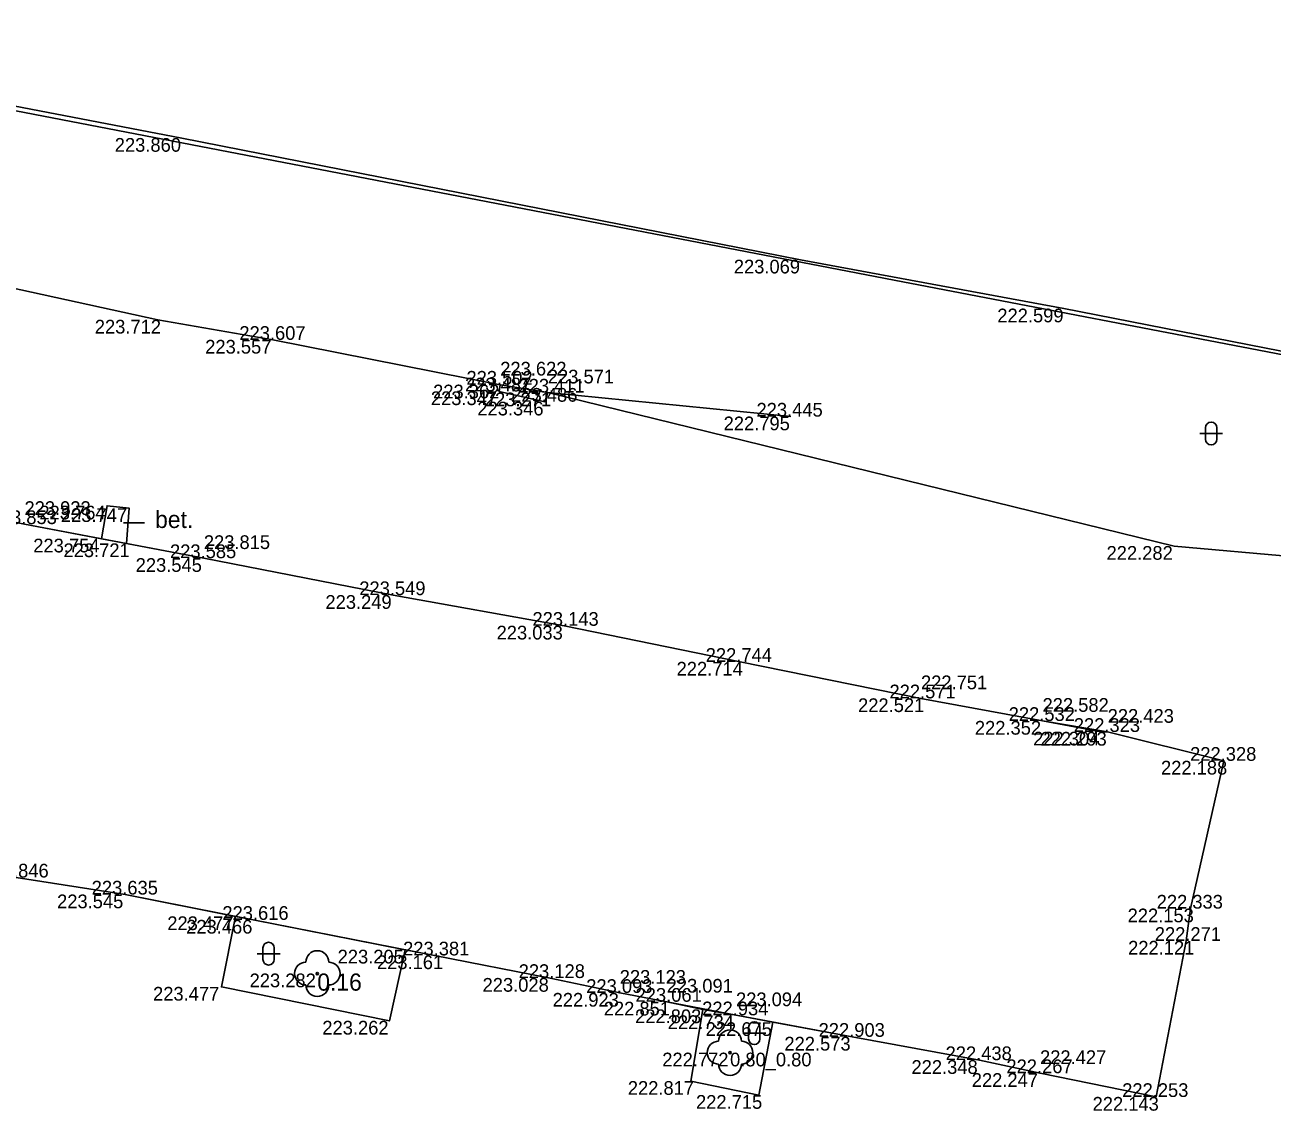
# Model space of a CAD drawing. Extents: x -599516 to -599132, y -1163668 to -1163119.
# Drawn here: x -599329.8 to -599302.48, y -1163179.4 to -1163155.61 of the extents above; entities that cross this region are included whole.
import ezdxf

# ---------------------------------------------------------------- set-up
doc = ezdxf.new("R2010")
doc.units = 0
for name, color, linetype in [('_ZEMERENI OBLAST', 7, 'Continuous'), ('Bod-oznac1', 7, 'Continuous'), ('Bod-oznac2', 7, 'Continuous'), ('Bod-oznac3', 7, 'Continuous'), ('Bod-vyska1', 7, 'Continuous'), ('Bod-vyska2', 7, 'Continuous'), ('Bod-vyska3', 7, 'Continuous'), ('Z_cela-hrobu-dolni-linie', 7, 'Continuous'), ('Z_cela-hrobu-horni-linie', 7, 'Continuous'), ('Z_komunikace', 7, 'Continuous'), ('Z_kultury-znacky', 7, 'Continuous'), ('Z_nove-stromy-prumer-kmene', 7, 'Continuous'), ('Z_obvod-kmene-spodek-ve-vysce1_2m', 7, 'Continuous'), ('Z_popis-budov-povrchu', 7, 'Continuous'), ('Z_povrchy-rozhrani-typu', 7, 'Continuous'), ('Z_stromy-kere', 7, 'Continuous'), ('Z_stromy-nove-vysazene', 7, 'Continuous'), ('Z_vol-lin-odkazova-cara', 7, 'Continuous'), ('Z_zdi-ohradni', 7, 'Continuous'), ('Z_zpevnene-plochy', 7, 'Continuous')]:
    doc.layers.add(name, color=color, linetype=linetype)

msp = doc.modelspace()

# ---------------------------------------------------------------- linework, layer by layer
at = {"layer": '_ZEMERENI OBLAST'}
msp.add_lwpolyline([(-599246.21, -1163173.61), (-599310.76, -1163161.2), (-599382.471, -1163147.382), (-599418.511, -1163140.298), (-599415.805, -1163126.425), (-599441.73, -1163121.594), (-599445.004, -1163135.25), (-599483.712, -1163127.751), (-599506.25, -1163123.345), (-599510.771, -1163146.476), (-599502.636, -1163301.975), (-599510.038, -1163302.355), (-599510.12, -1163309.17), (-599515.16, -1163309.664), (-599511.204, -1163380.278), (-599506.35, -1163380.56), (-599506.01, -1163391.1), (-599497.946, -1163390.674), (-599491.96, -1163502.01)], dxfattribs=at)
at = {"layer": 'Bod-oznac1'}
for p, q in [((-599326.361, -1163158.089), (-599326.361, -1163158.089)), ((-599312.815, -1163160.754), (-599312.815, -1163160.754)), ((-599307.042, -1163161.825), (-599307.042, -1163161.825)), ((-599326.887, -1163162.07), (-599326.887, -1163162.07)), ((-599324.365, -1163162.509), (-599324.365, -1163162.509)), ((-599319.412, -1163163.637), (-599319.412, -1163163.637)), ((-599319.387, -1163163.49), (-599319.387, -1163163.49)), ((-599318.345, -1163163.663), (-599318.345, -1163163.663)), ((-599318.407, -1163163.863), (-599318.407, -1163163.863)), ((-599313.023, -1163164.189), (-599313.023, -1163164.189)), ((-599327.997, -1163166.141), (-599327.997, -1163166.141)), ((-599327.512, -1163166.196), (-599327.512, -1163166.196)), ((-599328.119, -1163166.863), (-599328.119, -1163166.863)), ((-599327.573, -1163166.966), (-599327.573, -1163166.966)), ((-599304.627, -1163167.024), (-599304.627, -1163167.024)), ((-599325.878, -1163167.289), (-599325.878, -1163167.289)), ((-599321.733, -1163168.099), (-599321.733, -1163168.099)), ((-599317.987, -1163168.77), (-599317.987, -1163168.77)), ((-599314.134, -1163169.56), (-599314.134, -1163169.56)), ((-599310.173, -1163170.359), (-599310.173, -1163170.359)), ((-599307.511, -1163170.854), (-599307.511, -1163170.854)), ((-599306.225, -1163171.091), (-599306.225, -1163171.091)), ((-599306.085, -1163171.094), (-599306.085, -1163171.094)), ((-599303.538, -1163171.727), (-599303.538, -1163171.727)), ((-599327.599, -1163174.655), (-599327.599, -1163174.655)), ((-599325.182, -1163175.133), (-599325.182, -1163175.133)), ((-599304.27, -1163174.963), (-599304.27, -1163174.963)), ((-599324.795, -1163175.21), (-599324.795, -1163175.21)), ((-599304.363, -1163175.67), (-599304.363, -1163175.67)), ((-599321.468, -1163175.865), (-599321.468, -1163175.865)), ((-599320.825, -1163175.988), (-599320.825, -1163175.988)), ((-599323.394, -1163176.385), (-599323.394, -1163176.385)), ((-599318.294, -1163176.483), (-599318.294, -1163176.483)), ((-599325.493, -1163176.678), (-599325.493, -1163176.678)), ((-599316.77, -1163176.81), (-599316.77, -1163176.81)), ((-599315.742, -1163177.003), (-599315.742, -1163177.003)), ((-599314.954, -1163177.171), (-599314.954, -1163177.171)), ((-599314.224, -1163177.3), (-599314.224, -1163177.3)), ((-599321.813, -1163177.421), (-599321.813, -1163177.421)), ((-599313.417, -1163177.452), (-599313.417, -1163177.452)), ((-599311.681, -1163177.771), (-599311.681, -1163177.771)), ((-599314.354, -1163178.118), (-599314.354, -1163178.118)), ((-599308.888, -1163178.282), (-599308.888, -1163178.282)), ((-599307.566, -1163178.567), (-599307.566, -1163178.567)), ((-599315.214, -1163178.741), (-599315.214, -1163178.741)), ((-599313.721, -1163179.047), (-599313.721, -1163179.047)), ((-599305.026, -1163179.088), (-599305.026, -1163179.088))]:
    msp.add_line(p, q, dxfattribs=at)
at = {"layer": 'Bod-oznac2'}
for p, q in [((-599324.365, -1163162.509), (-599324.365, -1163162.509)), ((-599319.412, -1163163.637), (-599319.412, -1163163.637)), ((-599319.387, -1163163.49), (-599319.387, -1163163.49)), ((-599318.345, -1163163.663), (-599318.345, -1163163.663)), ((-599318.407, -1163163.863), (-599318.407, -1163163.863)), ((-599313.023, -1163164.189), (-599313.023, -1163164.189)), ((-599325.878, -1163167.289), (-599325.878, -1163167.289)), ((-599321.733, -1163168.099), (-599321.733, -1163168.099)), ((-599317.987, -1163168.77), (-599317.987, -1163168.77)), ((-599314.134, -1163169.56), (-599314.134, -1163169.56)), ((-599310.173, -1163170.359), (-599310.173, -1163170.359)), ((-599307.511, -1163170.854), (-599307.511, -1163170.854)), ((-599306.085, -1163171.094), (-599306.085, -1163171.094)), ((-599303.538, -1163171.727), (-599303.538, -1163171.727)), ((-599327.599, -1163174.655), (-599327.599, -1163174.655)), ((-599304.27, -1163174.963), (-599304.27, -1163174.963)), ((-599324.795, -1163175.21), (-599324.795, -1163175.21)), ((-599304.363, -1163175.67), (-599304.363, -1163175.67)), ((-599320.825, -1163175.988), (-599320.825, -1163175.988)), ((-599318.294, -1163176.483), (-599318.294, -1163176.483)), ((-599316.77, -1163176.81), (-599316.77, -1163176.81)), ((-599315.742, -1163177.003), (-599315.742, -1163177.003)), ((-599314.224, -1163177.3), (-599314.224, -1163177.3)), ((-599311.681, -1163177.771), (-599311.681, -1163177.771)), ((-599308.888, -1163178.282), (-599308.888, -1163178.282)), ((-599307.566, -1163178.567), (-599307.566, -1163178.567)), ((-599305.026, -1163179.088), (-599305.026, -1163179.088))]:
    msp.add_line(p, q, dxfattribs=at)
at = {"layer": 'Bod-oznac3'}
for p, q in [((-599319.387, -1163163.49), (-599319.387, -1163163.49)), ((-599318.345, -1163163.663), (-599318.345, -1163163.663)), ((-599325.878, -1163167.289), (-599325.878, -1163167.289)), ((-599310.173, -1163170.359), (-599310.173, -1163170.359)), ((-599307.511, -1163170.854), (-599307.511, -1163170.854)), ((-599306.085, -1163171.094), (-599306.085, -1163171.094)), ((-599316.77, -1163176.81), (-599316.77, -1163176.81)), ((-599315.742, -1163177.003), (-599315.742, -1163177.003)), ((-599314.224, -1163177.3), (-599314.224, -1163177.3)), ((-599307.566, -1163178.567), (-599307.566, -1163178.567))]:
    msp.add_line(p, q, dxfattribs=at)
at = {"layer": 'Z_cela-hrobu-dolni-linie'}
msp.add_line((-599327.573, -1163166.966), (-599328.119, -1163166.863), dxfattribs=at)
for points in [[(-599313.023, -1163164.189), (-599318.345, -1163163.663), (-599319.387, -1163163.49)], [(-599325.182, -1163175.133), (-599324.795, -1163175.21), (-599321.468, -1163175.865)], [(-599314.954, -1163177.171), (-599314.224, -1163177.3), (-599313.417, -1163177.452)]]:
    msp.add_lwpolyline(points, dxfattribs=at)
at = {"layer": 'Z_cela-hrobu-horni-linie'}
for p, q in [((-599317.987, -1163168.77), (-599321.733, -1163168.099)), ((-599314.134, -1163169.56), (-599317.987, -1163168.77))]:
    msp.add_line(p, q, dxfattribs=at)
for points in [[(-599313.023, -1163164.189), (-599318.345, -1163163.663), (-599319.387, -1163163.49), (-599324.365, -1163162.509)], [(-599321.733, -1163168.099), (-599325.878, -1163167.289), (-599325.878, -1163167.289), (-599329.806, -1163166.543), (-599329.806, -1163166.543), (-599332.367, -1163166.038)], [(-599314.134, -1163169.56), (-599310.173, -1163170.359), (-599310.173, -1163170.359), (-599307.511, -1163170.854), (-599307.511, -1163170.854), (-599306.085, -1163171.094), (-599306.085, -1163171.094), (-599303.538, -1163171.727), (-599304.27, -1163174.963)], [(-599324.795, -1163175.21), (-599327.599, -1163174.655)], [(-599320.825, -1163175.988), (-599324.795, -1163175.21)], [(-599304.363, -1163175.67), (-599305.026, -1163179.088), (-599307.566, -1163178.567), (-599307.566, -1163178.567), (-599308.888, -1163178.282)], [(-599311.681, -1163177.771), (-599314.224, -1163177.3), (-599314.224, -1163177.3), (-599315.742, -1163177.003), (-599315.742, -1163177.003), (-599316.77, -1163176.81), (-599316.77, -1163176.81), (-599318.294, -1163176.483), (-599320.825, -1163175.988)]]:
    msp.add_lwpolyline(points, dxfattribs=at)
at = {"layer": 'Z_komunikace'}
for points in [[(-599318.345, -1163163.663), (-599318.407, -1163163.863), (-599319.412, -1163163.637), (-599319.387, -1163163.49), (-599324.365, -1163162.509), (-599326.887, -1163162.07), (-599331.661, -1163161.023), (-599334.295, -1163160.601), (-599343.555, -1163158.724), (-599347.526, -1163157.941), (-599355.139, -1163156.542), (-599355.776, -1163156.429)], [(-599350.949, -1163162.537), (-599348.273, -1163162.99), (-599344.246, -1163163.763), (-599341.621, -1163164.249), (-599340.597, -1163164.419), (-599340.446, -1163163.738), (-599339.942, -1163163.851), (-599340.058, -1163164.536), (-599339.005, -1163164.764), (-599337.656, -1163165.017), (-599335.018, -1163165.53), (-599333.752, -1163165.793), (-599332.367, -1163166.038), (-599329.806, -1163166.543), (-599328.119, -1163166.863)], [(-599287.479, -1163169.726), (-599290.103, -1163169.086), (-599296.726, -1163167.729), (-599304.627, -1163167.024), (-599318.345, -1163163.663)], [(-599327.573, -1163166.966), (-599325.878, -1163167.289), (-599321.733, -1163168.099), (-599317.987, -1163168.77), (-599314.134, -1163169.56), (-599310.173, -1163170.359), (-599307.511, -1163170.854), (-599306.225, -1163171.091), (-599306.085, -1163171.094), (-599303.538, -1163171.727)], [(-599325.182, -1163175.133), (-599327.599, -1163174.655), (-599329.985, -1163174.282), (-599331.641, -1163174.239), (-599331.867, -1163175.607), (-599333.3, -1163175.262), (-599333.081, -1163173.758), (-599335.268, -1163173.304), (-599337.854, -1163172.76), (-599339.178, -1163172.519), (-599340.818, -1163172.194), (-599341.143, -1163173.716), (-599342.602, -1163173.415), (-599342.442, -1163171.866), (-599344.484, -1163171.488), (-599345.521, -1163171.291)], [(-599305.026, -1163179.088), (-599304.363, -1163175.67), (-599304.27, -1163174.963), (-599303.538, -1163171.727)], [(-599305.026, -1163179.088), (-599307.566, -1163178.567), (-599308.888, -1163178.282), (-599311.681, -1163177.771), (-599313.417, -1163177.452), (-599313.721, -1163179.047), (-599315.214, -1163178.741), (-599314.954, -1163177.171), (-599315.742, -1163177.003), (-599316.77, -1163176.81), (-599318.294, -1163176.483), (-599320.825, -1163175.988), (-599321.468, -1163175.865), (-599321.813, -1163177.421), (-599325.493, -1163176.678), (-599325.182, -1163175.133)]]:
    msp.add_lwpolyline(points, dxfattribs=at)
at = {"layer": 'Z_kultury-znacky'}
for p, q in [((-599303.942, -1163164.433), (-599303.942, -1163164.683)), ((-599303.692, -1163164.433), (-599303.692, -1163164.683)), ((-599304.067, -1163164.558), (-599303.567, -1163164.558)), ((-599324.71, -1163175.95), (-599324.21, -1163175.95)), ((-599324.585, -1163175.825), (-599324.585, -1163176.075)), ((-599324.335, -1163175.825), (-599324.335, -1163176.075)), ((-599313.949, -1163177.566), (-599313.949, -1163177.816)), ((-599313.699, -1163177.566), (-599313.699, -1163177.816)), ((-599314.074, -1163177.691), (-599313.574, -1163177.691))]:
    msp.add_line(p, q, dxfattribs=at)
for centre, start, end in [((-599303.817, -1163164.433), 0, 180), ((-599303.817, -1163164.683), 180, 0), ((-599324.46, -1163175.825), 0, 180), ((-599324.46, -1163176.075), 180, 0), ((-599313.824, -1163177.566), 0, 180), ((-599313.824, -1163177.816), 180, 0)]:
    msp.add_arc(centre, 0.125, start, end, dxfattribs=at)
at = {"layer": 'Z_povrchy-rozhrani-typu'}
msp.add_lwpolyline([(-599328.119, -1163166.863), (-599327.997, -1163166.141), (-599327.512, -1163166.196), (-599327.573, -1163166.966)], dxfattribs=at)
at = {"layer": 'Z_stromy-kere'}
msp.add_circle((-599314.354, -1163178.118), 0.025, dxfattribs=at)
for centre, start, end in [((-599314.354, -1163177.868), 0, 180), ((-599314.604, -1163178.118), 90, 270), ((-599314.104, -1163178.118), 270, 90), ((-599314.354, -1163178.368), 180, 0)]:
    msp.add_arc(centre, 0.25, start, end, dxfattribs=at)
at = {"layer": 'Z_stromy-nove-vysazene'}
msp.add_circle((-599323.394, -1163176.385), 0.025, dxfattribs=at)
for centre, start, end in [((-599323.394, -1163176.135), 0, 180), ((-599323.644, -1163176.385), 90, 270), ((-599323.144, -1163176.385), 270, 90), ((-599323.394, -1163176.635), 180, 0)]:
    msp.add_arc(centre, 0.25, start, end, dxfattribs=at)
at = {"layer": 'Z_vol-lin-odkazova-cara'}
msp.add_line((-599327.639, -1163166.512), (-599327.18, -1163166.512), dxfattribs=at)
at = {"layer": 'Z_zdi-ohradni'}
for points in [[(-599414.8, -1163140.976), (-599394.798, -1163144.985), (-599376.174, -1163148.484), (-599363.541, -1163150.911), (-599348.224, -1163153.888), (-599326.361, -1163158.089), (-599312.815, -1163160.754)], [(-599298.256, -1163163.544), (-599307.042, -1163161.825), (-599312.815, -1163160.754)]]:
    msp.add_lwpolyline(points, dxfattribs=at)
at = {"layer": 'Z_zpevnene-plochy'}
msp.add_lwpolyline([(-599319.387, -1163163.49), (-599319.412, -1163163.637), (-599318.407, -1163163.863), (-599318.345, -1163163.663)], dxfattribs=at)

# ---------------------------------------------------------------- texts
at = {"layer": 'Bod-vyska1'}
for s, p in [('223.860', (-599327.829, -1163158.389)), ('223.069', (-599314.272, -1163161.054)), ('223.712', (-599328.266, -1163162.37)), ('222.599', (-599308.501, -1163162.125)), ('223.557', (-599325.848, -1163162.809)), ('223.347', (-599320.907, -1163163.937)), ('223.362', (-599320.857, -1163163.79)), ('223.271', (-599319.724, -1163163.963)), ('223.346', (-599319.889, -1163164.163)), ('222.795', (-599314.495, -1163164.489)), ('223.764', (-599329.48, -1163166.441)), ('223.747', (-599329.009, -1163166.496)), ('223.754', (-599329.614, -1163167.163)), ('223.721', (-599328.952, -1163167.266)), ('222.282', (-599306.109, -1163167.324)), ('223.545', (-599327.371, -1163167.589)), ('223.249', (-599323.215, -1163168.399)), ('223.033', (-599319.467, -1163169.07)), ('222.714', (-599315.525, -1163169.86)), ('222.521', (-599311.551, -1163170.659)), ('222.352', (-599308.993, -1163171.154)), ('222.304', (-599307.716, -1163171.391)), ('222.293', (-599307.555, -1163171.394)), ('222.188', (-599304.916, -1163172.027)), ('223.545', (-599329.092, -1163174.955)), ('223.477', (-599326.679, -1163175.433)), ('222.153', (-599305.648, -1163175.263)), ('223.466', (-599326.265, -1163175.51)), ('222.121', (-599305.637, -1163175.97)), ('223.205', (-599322.948, -1163176.165)), ('223.161', (-599322.087, -1163176.288)), ('223.282', (-599324.876, -1163176.685)), ('223.028', (-599319.774, -1163176.783)), ('223.477', (-599326.99, -1163176.978)), ('222.923', (-599318.24, -1163177.11)), ('222.851', (-599317.12, -1163177.303)), ('222.803', (-599316.434, -1163177.471)), ('222.734', (-599315.719, -1163177.6)), ('223.262', (-599323.283, -1163177.721)), ('222.675', (-599314.889, -1163177.752)), ('222.573', (-599313.164, -1163178.071)), ('222.772', (-599315.839, -1163178.418)), ('222.348', (-599310.381, -1163178.582)), ('222.247', (-599309.061, -1163178.867)), ('222.817', (-599316.593, -1163179.041)), ('222.715', (-599315.1, -1163179.347)), ('222.143', (-599306.415, -1163179.388))]:
    msp.add_text(s, height=0.3, dxfattribs=at).set_placement(p)
at = {"layer": 'Bod-vyska2'}
for s, p in [('223.607', (-599325.1, -1163162.509)), ('223.487', (-599320.159, -1163163.637)), ('223.502', (-599320.127, -1163163.49)), ('223.411', (-599318.987, -1163163.663)), ('223.486', (-599319.148, -1163163.863)), ('223.445', (-599313.775, -1163164.189)), ('223.853', (-599330.547, -1163166.543)), ('223.585', (-599326.619, -1163167.289)), ('223.549', (-599322.474, -1163168.099)), ('223.143', (-599318.681, -1163168.77)), ('222.744', (-599314.887, -1163169.56)), ('222.571', (-599310.863, -1163170.359)), ('222.532', (-599308.252, -1163170.854)), ('222.323', (-599306.826, -1163171.094)), ('222.328', (-599304.279, -1163171.727)), ('223.846', (-599330.726, -1163174.282)), ('223.635', (-599328.334, -1163174.655)), ('222.333', (-599305.011, -1163174.963)), ('223.616', (-599325.472, -1163175.21)), ('222.271', (-599305.053, -1163175.67)), ('223.381', (-599321.514, -1163175.988)), ('223.128', (-599318.983, -1163176.483)), ('223.093', (-599317.504, -1163176.81)), ('223.061', (-599316.424, -1163177.003)), ('222.934', (-599314.965, -1163177.3)), ('222.903', (-599312.415, -1163177.771)), ('222.438', (-599309.634, -1163178.282)), ('222.267', (-599308.302, -1163178.567)), ('222.253', (-599305.767, -1163179.088))]:
    msp.add_text(s, height=0.3, dxfattribs=at).set_placement(p)
at = {"layer": 'Bod-vyska3'}
for s, p in [('223.622', (-599319.387, -1163163.29)), ('223.571', (-599318.345, -1163163.463)), ('223.923', (-599329.806, -1163166.343)), ('223.815', (-599325.878, -1163167.089)), ('222.751', (-599310.173, -1163170.159)), ('222.582', (-599307.511, -1163170.654)), ('222.423', (-599306.085, -1163170.894)), ('223.123', (-599316.77, -1163176.61)), ('223.091', (-599315.742, -1163176.803)), ('223.094', (-599314.224, -1163177.1)), ('222.427', (-599307.566, -1163178.367))]:
    msp.add_text(s, height=0.3, dxfattribs=at).set_placement(p)
at = {"layer": 'Z_nove-stromy-prumer-kmene'}
msp.add_text('0.16', height=0.375, dxfattribs=at).set_placement((-599323.394, -1163176.76))
at = {"layer": 'Z_obvod-kmene-spodek-ve-vysce1_2m'}
msp.add_text('0.80_0.80', height=0.3, dxfattribs=at).set_placement((-599314.354, -1163178.418))
at = {"layer": 'Z_popis-budov-povrchu'}
msp.add_text('bet.', height=0.375, dxfattribs=at).set_placement((-599326.946, -1163166.629))

doc.saveas('drawing.dxf')
